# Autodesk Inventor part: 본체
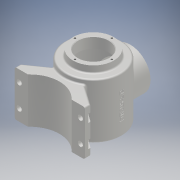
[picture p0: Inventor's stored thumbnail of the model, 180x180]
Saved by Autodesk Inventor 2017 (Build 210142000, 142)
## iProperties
Part Number: 본체
Material: 알루미늄 6061
Document SubType Name: Modeling
Designer: MRC
Density: 2.7 g/cm^3
Appearance: 알루미늄 - 평지
Mass: 1296.69 g
Surface Area: 1060.41 cm^2
Volume: 480.255 cm^3
Author: MRC
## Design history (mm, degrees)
sketch "스케치1"
  geometry: L1 (0, 50)-(0, -58); L2 (50, 50)-(50, -46.336); L3 (50, 50)-(0, 50); A1 r 113 centre (0, 55) between (0, -58) and (50, -46.336); 1 further point
  constraints: 6 end point, 2 point on circle, 2 point on line, 2 vertical, 1 centre point, 1 horizontal
  dimensions: "d0" = 108 distance of L1.start L1.end; "d1" = 50 distance of L1.start point (0, 0); "d3" = 100 diameter of L2 L1; "d4" = 113 radius of A1
revolve "회전1" sketch "스케치1" stored, may be unused: angle "d5" = 90 deg
feature "쉘1" dims "d6" = 7
sketch "스케치2"
  geometry: C1 r 36 at (0, 0); 1 further point
  constraints: 1 centre point, 1 coincident
  dimensions: "d7" = 72 diameter of C1
extrude "돌출1" join sketch "스케치2" distance "d8" = 12; taper "d9" = 0 deg
sketch "스케치3"
  geometry: C1 r 27 at (0, 0); 1 further point
  constraints: 1 centre point, 1 coincident
  dimensions: "d10" = 54 diameter of C1
extrude "돌출2" cut sketch "스케치3" distance "d11" = 19; taper "d12" = 0 deg
sketch "스케치4"
  geometry: L1 (-26.694, -42.278)-(-62, -67); L2 (-62, -67)-(-62, -77); L3 (-62, -77)-(-38.5, -77); L4 (38.5, -77)-(62, -77); L5 (62, -77)-(62, -67); L6 (62, -67)-(26.694, -42.278); A1 r 52.096 centre (0, -112.096) between (38.5, -77) and (-38.5, -77); A2 r 50 centre (0, 0) between (26.694, -42.278) and (-26.694, -42.278) reference; 1 further point
  constraints: 12 end point, 4 point on circle, 2 perpendicular, 1 centre point, 1 collinear, 1 horizontal, 1 vertical, 1 vertical alignment
  dimensions: "d13" = 10 distance of L4.end L5.end; "d14" = 77 distance of L4.start L3.end; "d15" = 55 deg angle of L5 L6; "d16" = 10 distance of L1.end L2.end; "d17" = 77 distance from line of L4 point (0, 0); "d18" = 77 distance from line of point (0, 0) L3; "d19" = 124 distance between parallel lines of L5 L2; "d20" = 17 distance edge to line of A1 L4; "d26" = 55 deg angle of L2 L1
extrude "돌출3" join sketch "스케치4" distance "d23" = 42; taper "d24" = 0 deg; dims "d88" = 38, "d89" = 0
node "작업 평면1"
sketch "스케치5"
  geometry: C1 r 36 at (-38.5, -42); 1 further point
  constraints: 1 centre point, 1 coincident
  dimensions: "d28" = 72 diameter of C1
extrude "돌출4" join sketch "스케치5" stored distance "d29" = 10; taper "d30" = 0 deg
sketch "스케치6"
  geometry: C1 r 27 at (0, 0); 1 further point
  constraints: 1 centre point, 1 coincident
  dimensions: "d31" = 54 diameter of C1
extrude "돌출5" cut sketch "스케치6" distance "d32" = 41.5; taper "d33" = 0 deg
sketch "스케치7" dims "d34" = 65
  geometry: 3 further points
  constraints: 2 horizontal alignment, 1 coincident, 2 other
hole "구멍1" sketch "스케치7" at (-32.5, 0) diameter "d35" = 3.242; stored, may be unused: countersink angle "d39" = 90 deg, drill point angle "d41" = 118 deg; dims "d36" = 8, "d37" = 4, "d38" = 2, "d40" = 10
sketch "스케치12" dims "d58" = 65
  geometry: 3 further points
  constraints: 2 vertical alignment, 1 coincident, 2 other
hole "구멍2" sketch "스케치12" at (0, 32.5) diameter "d59" = 3.242; stored, may be unused: countersink angle "d63" = 90 deg, drill point angle "d65" = 118 deg; dims "d60" = 8, "d61" = 4, "d62" = 2, "d64" = 10
sketch "스케치9"
  geometry: L1 (23.5, -80)-(23.5, 0) reference; L2 (23.5, -80)-(0, -80) reference; C1 r 4.5 at (15.5, -60); 1 further point
  constraints: 1 centre point
  dimensions: "d49" = 9 diameter of C1; "d50" = 8 distance from line of L1 C1.centre; "d51" = 20 distance from line of L2 C1.centre
extrude "돌출6" cut sketch "스케치9" distance "d52" = 6; taper "d53" = 0 deg
sketch "스케치13"
  geometry: L1 (0, 0)-(24.644, 0); L2 (0, -7)-(24.644, -7); L3 (24.644, 7)-(0, 7); L4 (8, -20)-(8, 60) reference; L5 (-27.306, -20)-(8, -20) reference; A1 r 7 centre (0, 0) between (0, 7) and (0, -7); A2 r 7 centre (24.644, 0) between (24.644, -7) and (24.644, 7); 2 further points
  constraints: 8 end point, 4 point on circle, 4 tangent, 2 centre point, 1 horizontal, 1 midpoint, 1 parallel
  dimensions: "d69" = 14 diameter of A2; "d70" = 8 distance from line of L4 L1.start; "d71" = 20 distance from line of L5 L1.start; "d72" = 24.64379 distance of L3.start L3.end
extrude "돌출8" cut sketch "스케치13" distance "d73" = 20; taper "d74" = 0 deg
fillet "모깎기1" dims "d78" = 3
fillet "모깎기2" dims "d79" = 3
fillet "모깎기3" dims "d80" = 3
fillet "모깎기4" dims "d81" = 3
fillet "모깎기5" dims "d82" = 3
chamfer "모따기1" distance "d83" = 1; stored, may be unused: second distance "d84" = 2, angle "d85" = 45 deg
fillet "모깎기6" dims "d86" = 3
node "작업 평면3"
sketch "스케치14"
  geometry: L1 (36, 62)-(-36, 62) reference; 2 further points
  constraints: 2 coincident, 1 other
  dimensions: "d90" = 62 distance from line of point (0, 0) L1 (derived)
feature "엠보싱1" sketch "스케치14" dims "d91" = 0.5, "d92" = 0
node "솔리드1"
pattern_circular "원형 패턴1" dims angle "d43" = 360 deg
pattern_circular "원형 패턴2" dims angle "d67" = 360 deg
pattern_linear "직사각형 패턴1" dims "d77" = 40
mirror "미러1"
other parameters: "d27" = -142, "d87" = 82.25
